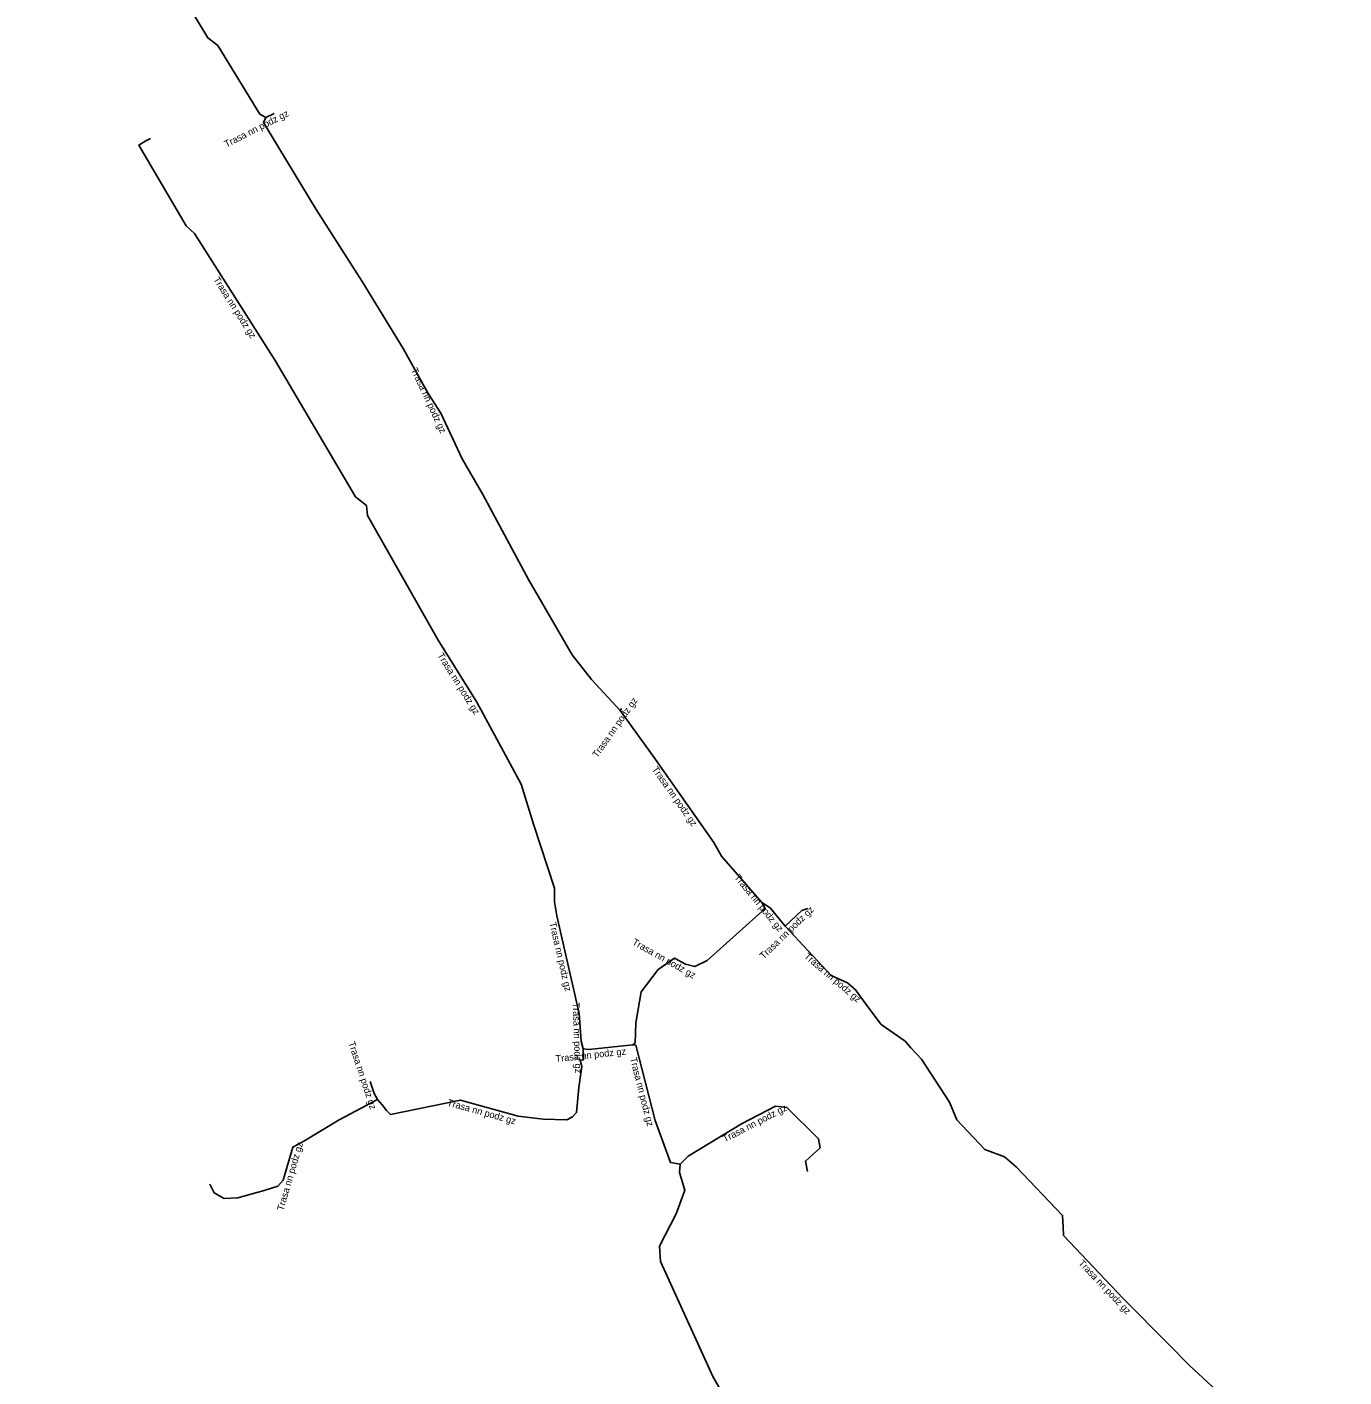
# Model space of a CAD drawing. Extents: x -746106 to -745701, y -1027695 to -1027301.
# Drawn here: x -745897.9 to -745801.8, y -1027497.7 to -1027399.2 of the extents above; entities that cross this region are included whole.
import ezdxf

# ---------------------------------------------------------------- set-up
doc = ezdxf.new("R2010")
doc.units = 0
doc.layers.add('Popiskový text - Ostatní atributy Trasy', color=7, linetype='Continuous')
doc.layers.add('Spojnice NN', color=7, linetype='Continuous')

msp = doc.modelspace()

# ---------------------------------------------------------------- linework, layer by layer
at = {"layer": 'Spojnice NN'}
for points in [[(-745895.734, -1027377.966), (-745896.526, -1027377.796), (-745897.564, -1027378.612), (-745897.883, -1027379.18), (-745897.678, -1027379.881), (-745896.555, -1027381.729), (-745895.957, -1027382.524), (-745892.205, -1027387.837), (-745887.724, -1027394.922), (-745884.676, -1027399.981), (-745883.955, -1027400.552), (-745880.892, -1027405.551), (-745880.454, -1027405.816)], [(-745880.454, -1027405.816), (-745880.626, -1027406.16), (-745876.778, -1027412.529), (-745873.425, -1027417.77), (-745870.422, -1027422.657), (-745868.615, -1027425.957), (-745867.681, -1027427.394), (-745866.135, -1027430.713), (-745864.627, -1027433.33), (-745861.284, -1027439.532), (-745858.1, -1027445.033), (-745856.688, -1027446.816), (-745854.598, -1027449.072)], [(-745880.454, -1027405.816), (-745879.857, -1027405.513)], [(-745873.11, -1027434.12), (-745873.92, -1027433.48), (-745879.77, -1027423.55), (-745885.67, -1027414.27), (-745886.26, -1027413.72), (-745889.73, -1027407.82), (-745889.22, -1027407.5), (-745888.87, -1027407.33)], [(-745859.4, -1027462.721), (-745859.4, -1027462.05), (-745860.91, -1027457.38), (-745861.83, -1027454.45), (-745865.05, -1027448.48), (-745867.88, -1027443.96), (-745873.03, -1027434.85), (-745873.11, -1027434.12)], [(-745854.598, -1027449.072), (-745854.51, -1027448.947)], [(-745854.598, -1027449.072), (-745852.192, -1027452.408), (-745847.754, -1027458.706), (-745847.21, -1027459.712), (-745844.25, -1027463.106)], [(-745857.296, -1027473.772), (-745857.43, -1027473.22), (-745857.58, -1027471.2), (-745859.22, -1027464.06), (-745859.4, -1027463.04), (-745859.4, -1027462.721)], [(-745844.25, -1027463.106), (-745844.012, -1027463.545), (-745848.259, -1027467.332), (-745849.154, -1027467.778), (-745849.821, -1027467.604), (-745850.63, -1027467.149), (-745851.816, -1027467.982), (-745853.055, -1027469.617), (-745853.445, -1027471.881), (-745853.496, -1027473.336), (-745853.664, -1027473.485)], [(-745844.25, -1027463.106), (-745843.652, -1027463.487), (-745842.547, -1027464.832)], [(-745842.547, -1027464.832), (-745841.35, -1027463.673), (-745840.892, -1027463.538)], [(-745842.547, -1027464.832), (-745839.189, -1027468.416), (-745838.007, -1027468.965), (-745837.416, -1027469.465), (-745836.442, -1027470.819), (-745835.537, -1027471.992), (-745833.797, -1027473.221), (-745833.377, -1027473.697)], [(-745857.467, -1027474.595), (-745857.269, -1027474.569), (-745857.296, -1027473.772)], [(-745853.664, -1027473.485), (-745856.878, -1027473.832), (-745857.296, -1027473.772)], [(-745853.664, -1027473.485), (-745853.459, -1027473.502), (-745852.052, -1027479.015), (-745850.926, -1027482.068), (-745850.229, -1027482.2)], [(-745833.377, -1027473.697), (-745832.612, -1027474.523), (-745830.56, -1027477.677), (-745830.022, -1027478.956), (-745827.987, -1027481.125), (-745826.539, -1027481.646), (-745825.695, -1027482.379), (-745822.306, -1027485.931), (-745822.271, -1027486.768), (-745822.238, -1027487.409), (-745817.88, -1027491.993), (-745814.573, -1027495.33), (-745813.054, -1027496.89), (-745811.104, -1027498.69), (-745808.128, -1027502.296), (-745805.968, -1027504.899), (-745801.773, -1027509.962)], [(-745857.467, -1027474.595), (-745857.509, -1027474.612), (-745857.403, -1027475.053), (-745857.607, -1027476.609), (-745857.783, -1027478.42), (-745858.063, -1027478.734), (-745858.5, -1027478.96), (-745860.209, -1027478.919), (-745862.047, -1027478.694), (-745866.252, -1027477.518), (-745871.354, -1027478.579), (-745871.657, -1027478.275), (-745871.967, -1027477.863), (-745872.3, -1027477.471)], [(-745872.3, -1027477.471), (-745872.546, -1027477.024), (-745872.834, -1027476.147)], [(-745872.3, -1027477.471), (-745875.096, -1027478.957), (-745877.683, -1027480.521), (-745878.492, -1027480.949), (-745879.194, -1027483.37), (-745879.589, -1027483.797), (-745880.573, -1027484.108), (-745882.497, -1027484.648), (-745883.494, -1027484.696), (-745884.234, -1027484.292), (-745884.53, -1027483.643)], [(-745850.229, -1027482.2), (-745849.634, -1027481.617), (-745845.744, -1027479.252), (-745843.26, -1027477.968), (-745842.428, -1027478.048), (-745840.115, -1027480.333), (-745840.006, -1027481.008), (-745841.059, -1027481.972), (-745840.913, -1027482.735)], [(-745853.61, -1027553.12), (-745853.041, -1027552.293), (-745850.882, -1027548.602), (-745848.014, -1027543.542), (-745844.953, -1027537.291), (-745842.98, -1027531.806), (-745841.482, -1027525.784), (-745841.162, -1027521.625), (-745841.47, -1027519.578), (-745842.05, -1027511.804), (-745843.5, -1027506.493), (-745845.352, -1027502.013), (-745847.826, -1027497.687), (-745851.137, -1027490.418), (-745851.641, -1027489.286), (-745851.735, -1027488.177), (-745850.501, -1027485.822), (-745849.882, -1027484.088), (-745850.26, -1027482.805), (-745850.229, -1027482.2)]]:
    msp.add_lwpolyline(points, dxfattribs=at)

# ---------------------------------------------------------------- texts
at = {"layer": 'Popiskový text - Ostatní atributy Trasy'}
for rotation, p in [(26.90951, (-745883.333, -1027408.006)), (302.44722, (-745884.307, -1027417.624)), (294.97624, (-745869.878, -1027424.217)), (302.05094, (-745867.959, -1027445.059)), (54.85445, (-745856.264, -1027452.568)), (305.17113, (-745852.305, -1027453.375)), (309.4052, (-745846.299, -1027461.289)), (44.07595, (-745844.122, -1027467.262)), (282.936, (-745859.766, -1027464.584)), (330.64561, (-745853.763, -1027466.132)), (319.76799, (-745841.218, -1027467.099)), (271.94027, (-745858.061, -1027470.401)), (288.17978, (-745874.442, -1027473.332)), (6.16208, (-745859.282, -1027474.746)), (284.31711, (-745853.883, -1027474.467)), (344.37544, (-745867.26, -1027477.911)), (27.33481, (-745846.956, -1027480.61)), (73.82981, (-745879.172, -1027485.629)), (313.55222, (-745821.192, -1027489.452))]:
    msp.add_text('Trasa nn podz gz', height=0.5, rotation=rotation, dxfattribs=at).set_placement(p)

doc.saveas('drawing.dxf')
